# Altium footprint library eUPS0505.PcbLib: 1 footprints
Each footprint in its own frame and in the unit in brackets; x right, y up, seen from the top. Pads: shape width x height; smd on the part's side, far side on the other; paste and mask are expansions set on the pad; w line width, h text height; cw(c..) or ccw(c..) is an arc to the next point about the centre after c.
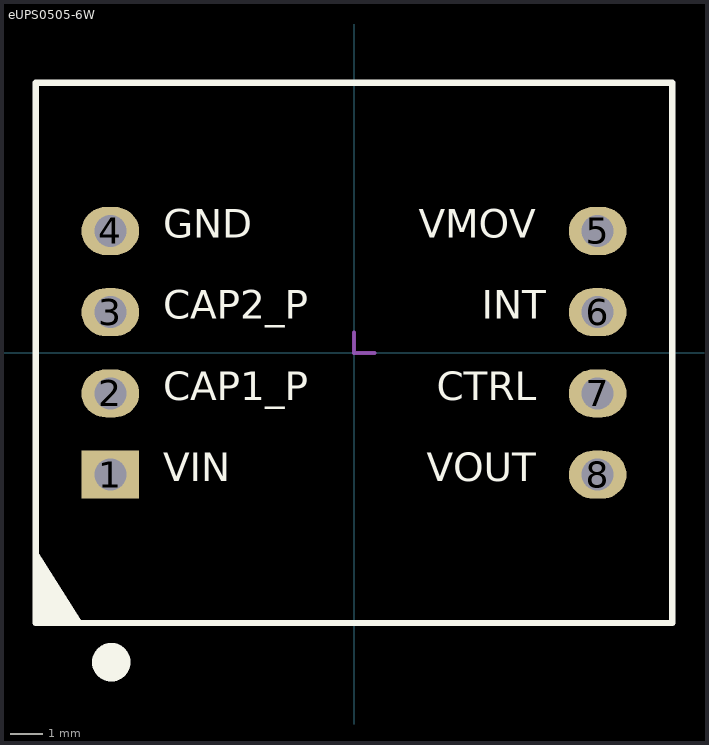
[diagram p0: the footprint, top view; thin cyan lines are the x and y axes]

## eUPS0505-6W [mm]
height 7.1
pads (8):
  rect 1.8x1.5 hole 1: 1(-7.62,-3.81)
  oval 1.8x1.5 hole 1: 2(-7.62,-1.27) 3(-7.62,1.27) 4(-7.62,3.81) 5(7.62,3.81) 6(7.62,1.27) 7(7.62,-1.27) 8(7.62,-3.81)
Top Overlay:
  circle w1: c-7.593,-9.675 r0.1
  region: -9.95,-6.12 -9.95,-8.45 -8.49,-8.45
  lines w0.2: -9.95,-8.45 9.95,-8.45 9.95,8.45 -9.95,8.45 -9.95,-8.45
  text "VMOV" at 2.032,3.302 h1.52
  text "VOUT" at 2.277,-4.318 h1.52
  text "CTRL" at 2.586,-1.778 h1.52
  text "INT" at 3.989,0.762 h1.52
  text "CAP1_P" at -5.969,-1.778 h1.52
  text "CAP2_P" at -5.969,0.762 h1.52
  text "GND" at -5.969,3.302 h1.52
  text "VIN" at -5.968,-4.318 h1.52
Mechanical 15:
  lines w0.127: 0,0.635 0,0 0.635,0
